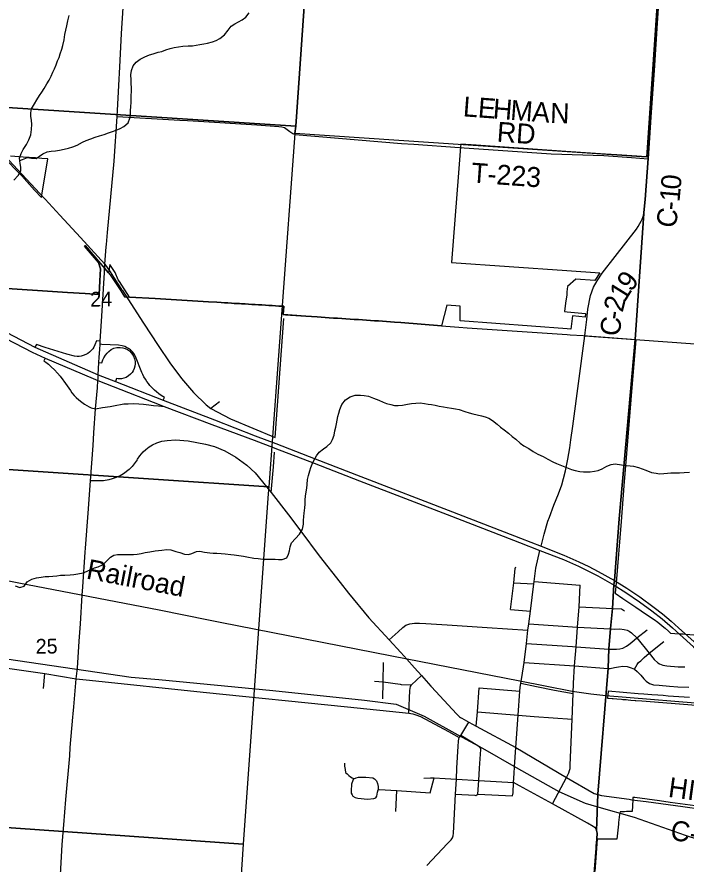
# Model space of a CAD drawing. Extents: x 114843 to 284848, y 317643 to 566895.
# Drawn here: x 253253 to 263305, y 341883 to 354619 of the extents above; entities that cross this region are included whole.
import ezdxf

# ---------------------------------------------------------------- set-up
doc = ezdxf.new("R2010")
doc.units = 0
for name, color, linetype in [('GM_X_City_Street', 7, 'Continuous'), ('GM_X_Corporation', 7, 'Continuous'), ('GM_X_County', 7, 'Continuous'), ('GM_X_County_Road', 7, 'Continuous'), ('GM_X_County_Road_Text', 7, 'Continuous'), ('GM_X_Interchange_Ramps', 7, 'Continuous'), ('GM_X_Minor_River', 7, 'Continuous'), ('GM_X_Rail_Line', 7, 'Continuous'), ('GM_X_Rail_Line_Text', 7, 'Continuous'), ('GM_X_Section', 7, 'Continuous'), ('GM_X_Section_Text', 7, 'Continuous'), ('GM_X_State_Route', 7, 'Continuous'), ('GM_X_Township', 7, 'Continuous'), ('GM_X_Township_Road', 7, 'Continuous'), ('GM_X_Township_Road_Text', 7, 'Continuous'), ('GM_X_US_Route', 7, 'Continuous')]:
    doc.layers.add(name, color=color, linetype=linetype)

msp = doc.modelspace()

# ---------------------------------------------------------------- linework, layer by layer
at = {"layer": 'GM_X_City_Street'}
for p, q in [((257133, 348296), (257263, 350085)), ((261785, 349824), (262542, 349768)), ((256296, 348834), (256164, 348733)), ((260716, 346113), (261017, 346097)), ((261022, 346129), (261713, 346076)), ((260670, 345711), (260966, 345685)), ((261699, 345750), (262204, 345725)), ((261653, 345149), (262147, 345116)), ((253652, 344524), (253674, 344750)), ((260197, 344531), (260809, 344482)), ((259366, 343176), (259468, 343178)), ((259462, 342954), (259519, 343179)), ((258944, 342674), (258960, 342987)), ((259842, 342933), (260131, 342917))]:
    msp.add_line(p, q, dxfattribs=at)
for points in [[(255061, 347963), (255066, 347971), (255101, 348021), (255150, 348079), (255190, 348117), (255241, 348157), (255291, 348185), (255354, 348215), (255430, 348240), (255510, 348253), (255633, 348263), (255826, 348245), (256087, 348197), (256223, 348161), (256377, 348097), (256542, 348000), (256706, 347881), (256834, 347765), (257072, 347471), (257331, 347132), (257517, 346888), (257792, 346519), (258110, 346115), (258232, 345954), (258539, 345587), (258845, 345252), (259019, 345062), (259110, 344962), (259223, 344835), (259330, 344716), (259472, 344559)], [(257072, 347471), (257105, 347855), (257122, 348074)], [(255061, 347963), (255059, 347961), (255028, 347919)], [(255028, 347919), (254984, 347860), (254939, 347813), (254854, 347749), (254801, 347720), (254745, 347694), (254685, 347673), (254631, 347659), (254552, 347645), (254359, 347647)], [(260836, 344690), (260871, 344912), (260906, 345199), (260929, 345401), (260941, 345495), (260966, 345685), (261017, 346097), (261022, 346129), (261046, 346330), (261110, 346598)], [(260670, 345711), (260716, 346113), (260738, 346326), (260749, 346353)], [(261616, 344603), (261630, 344862), (261653, 345149), (261672, 345446), (261699, 345750), (261713, 346076)], [(262204, 345725), (262335, 345719), (262379, 345691)], [(258845, 345252), (258978, 345377), (259049, 345441), (259095, 345474), (259154, 345496), (259225, 345506), (259300, 345503), (259398, 345501), (259717, 345481), (260319, 345441), (260929, 345401)], [(260941, 345495), (261672, 345446), (262172, 345420)], [(262147, 345116), (262261, 345114), (262312, 345117), (262356, 345129), (262411, 345159), (262446, 345185), (262493, 345220), (262566, 345284), (262719, 345406)], [(262172, 345420), (262237, 345417), (262311, 345418), (262375, 345412), (262419, 345401), (262451, 345384), (262488, 345360), (262566, 345284), (262751, 345055), (262828, 344961), (262880, 344911), (262907, 344893), (262958, 344874), (263018, 344865), (263188, 344851), (263288, 344847)], [(260906, 345199), (261600, 345153), (261653, 345149)], [(262529, 344811), (262571, 344884), (262593, 344912), (262624, 344941), (262677, 344988), (262751, 345055), (262971, 345227)], [(258750, 344365), (258754, 344624), (258759, 344914)], [(260871, 344912), (261630, 344862), (262134, 344826)], [(262134, 344826), (262167, 344824), (262228, 344837), (262290, 344851), (262356, 344857), (262422, 344852), (262481, 344835), (262529, 344811), (262572, 344779), (262626, 344725), (262672, 344668), (262707, 344632), (262755, 344599), (262817, 344577), (262903, 344571), (263056, 344557), (263184, 344549), (263348, 344542)], [(258625, 344633), (258754, 344624), (259010, 344588)], [(259140, 344151), (259155, 344492), (259163, 344552), (259178, 344577), (259330, 344716)], [(260747, 343636), (260783, 344122), (260809, 344482), (260813, 344537), (260822, 344601), (260836, 344690)], [(259010, 344588), (259027, 344585), (259178, 344577)], [(259472, 344559), (259483, 344547), (259855, 344140), (259880, 344118), (259902, 344098), (259917, 344088), (259937, 344076), (260040, 344017)], [(260152, 343955), (260173, 344174), (260197, 344531)], [(260822, 344601), (261058, 344553), (261328, 344497), (261608, 344447)], [(261298, 342787), (261428, 343034), (261509, 343183), (261542, 343256), (261553, 343288), (261562, 343318), (261565, 343370), (261592, 344063), (261608, 344447), (261616, 344603)], [(260173, 344174), (260783, 344122), (261024, 344102), (261592, 344063)], [(259885, 343727), (259885, 343738), (259896, 343784), (259921, 343816), (260040, 344017)], [(260040, 344017), (260152, 343955), (260747, 343636)], [(260220, 343611), (260217, 343624), (260202, 343641), (260176, 343659), (259921, 343816)], [(259410, 341863), (259722, 342191), (259776, 342248), (259794, 342276), (259806, 342307), (259809, 342349), (259842, 342933), (259855, 343160), (259863, 343325), (259882, 343656), (259885, 343727)], [(260747, 343636), (261509, 343183), (261927, 342946), (261981, 342930)], [(260176, 342932), (260193, 343139), (260204, 343327), (260221, 343606), (260220, 343611)], [(258172, 343398), (258172, 343354), (258182, 343304), (258190, 343262), (258212, 343242), (258238, 343214), (258264, 343196), (258290, 343178), (258310, 343168), (258316, 343164), (258349, 343182), (258385, 343192), (258423, 343192), (258495, 343190), (258597, 343179), (258623, 343165), (258653, 343135), (258671, 343095), (258681, 343047), (258679, 343000)], [(258310, 343168), (258297, 343138), (258281, 343086), (258273, 342986), (258274, 342962), (258275, 342950), (258289, 342924), (258299, 342906), (258335, 342882), (258373, 342872), (258517, 342860), (258615, 342868), (258643, 342880), (258657, 342902), (258669, 342962), (258679, 343000), (258695, 343004), (258960, 342987), (259462, 342954)], [(259468, 343178), (259519, 343179), (259684, 343171), (259855, 343160), (260193, 343139), (260715, 343110)], [(260700, 342910), (260709, 342952), (260715, 343110)], [(260131, 342917), (260145, 342916), (260176, 342932), (260700, 342910)], [(261964, 342260), (261971, 342344), (261963, 342385)]]:
    msp.add_lwpolyline(points, dxfattribs=at)
at = {"layer": 'GM_X_Corporation'}
for points in [[(262912, 355132), (262872, 354526), (262825, 353814), (262768, 352973), (262738, 352513), (262709, 352516), (262565, 352526), (262415, 352536), (262266, 352546), (262095, 352558), (261946, 352568), (261500, 352598), (260150, 352689), (259920, 352706), (259918, 352665), (259887, 352275), (259781, 350929), (261513, 350807), (262010, 350772), (261936, 350656), (261650, 350676), (261524, 350566), (261515, 350487), (261512, 350443), (261495, 350317), (261480, 350192), (261517, 350188), (261796, 350163), (261790, 350107), (261598, 350125), (261573, 349927), (261519, 349930), (259912, 350048), (259912, 350272), (259709, 350285), (259632, 349973), (259018, 350024), (258925, 350031), (258863, 350035), (258803, 350039), (258743, 350043), (258684, 350048), (258624, 350052), (258564, 350056), (258504, 350060), (258444, 350064), (258384, 350068), (258319, 350072), (258259, 350076), (258195, 350081), (258135, 350085), (258070, 350089), (258010, 350093), (257945, 350098), (257885, 350102), (257825, 350106), (257761, 350110), (257591, 350122), (257252, 350144), (257260, 350269), (257189, 350273), (257086, 350279), (257036, 350282), (256986, 350285), (256930, 350289), (256880, 350292), (256831, 350295), (256781, 350298), (256731, 350301), (256681, 350304), (256625, 350307), (256598, 350309), (256575, 350310), (256525, 350313), (256516, 350313), (256475, 350316), (256419, 350319), (256369, 350322), (256319, 350325), (256257, 350329), (256128, 350337), (255328, 350384), (254943, 350408), (254791, 350641), (254774, 350668), (254730, 350778), (254650, 350896), (254630, 350771), (254497, 350926), (254277, 351184), (254265, 351174), (254479, 350926), (254506, 350834), (254497, 350654), (254487, 350446), (254278, 350459), (254014, 350477), (253636, 350502), (252565, 350573)], [(253031, 352533), (253325, 352228), (253518, 352014), (253620, 351903), (253631, 351976), (253635, 351998), (253716, 352486), (253624, 352492), (253530, 352499), (253344, 352511), (253158, 352524)], [(252565, 350573), (253636, 350502), (254014, 350477), (254278, 350459), (254487, 350446), (254497, 350654), (254506, 350834), (254479, 350926), (254265, 351174), (254277, 351184), (254653, 350744), (254712, 350654), (254802, 350515), (254828, 350476), (254870, 350411), (254905, 350410), (254943, 350408), (255328, 350384), (256128, 350337), (256257, 350329), (256319, 350325), (256369, 350322), (256419, 350319), (256475, 350316), (256516, 350313), (256525, 350313), (256575, 350310), (256598, 350309), (256625, 350307), (256681, 350304), (256731, 350301), (256781, 350298), (256831, 350295), (256880, 350292), (256930, 350289), (256986, 350285), (257036, 350282), (257086, 350279), (257189, 350273), (257260, 350269), (257252, 350144), (257285, 350142), (257591, 350122), (257761, 350110), (257825, 350106), (257885, 350102), (257945, 350098), (258010, 350093), (258070, 350089), (258135, 350085), (258195, 350081), (258259, 350076), (258319, 350072), (258384, 350068), (258444, 350064), (258504, 350060), (258564, 350056), (258624, 350052), (258684, 350048), (258743, 350043), (258803, 350039), (258863, 350035), (258925, 350031), (259018, 350024), (259632, 349973), (259892, 349954), (260019, 349945), (261520, 349845), (261562, 349842), (261758, 349829), (262551, 349769), (262477, 348862), (262411, 348054), (262372, 347569), (262329, 347033), (262254, 346109), (262241, 345954), (262356, 345877), (262552, 345746), (262713, 345634), (262825, 345558), (262882, 345519), (262972, 345443), (262989, 345428), (263042, 345384), (263073, 345357), (263201, 345347), (263264, 345343), (263303, 345340), (263544, 345321)], [(263357, 344386), (263278, 344392), (263198, 344398), (263118, 344404), (263038, 344410), (262959, 344417), (262879, 344423), (262789, 344430), (262672, 344439), (262585, 344445), (262133, 344481), (262128, 344426), (262125, 344376), (262195, 344371), (262210, 344370), (262265, 344365), (262335, 344360), (262355, 344358), (262404, 344355), (262434, 344352), (262474, 344349), (262539, 344344), (262544, 344344), (262553, 344343), (262639, 344336), (262706, 344331), (263016, 344307), (263707, 344254)], [(263819, 342708), (263065, 342810), (262908, 342832), (262538, 342882), (262507, 342885), (262506, 342856), (262499, 342757), (262494, 342674), (262482, 342674), (262436, 342673), (262409, 342672), (262379, 342671), (262333, 342670), (262314, 342670), (262305, 342627), (262292, 342506), (262289, 342482), (262266, 342260), (261984, 342260), (261970, 342260), (261934, 341774)]]:
    msp.add_lwpolyline(points, dxfattribs=at)
at = {"layer": 'GM_X_County'}
for points in [[(262910, 355135), (262821, 353807), (262736, 352491), (262692, 351874), (262671, 351678), (262670, 351665), (262541, 349771), (262299, 347075), (262228, 346149), (262222, 346080), (262202, 345728), (262171, 345423), (262146, 345119), (262133, 344829), (261980, 342933), (261962, 342388), (261970, 342347), (261963, 342262), (261953, 342120), (261868, 341046)], [(261868, 341046), (261953, 342120), (261963, 342262), (261970, 342347), (261962, 342388), (261980, 342933), (262133, 344829), (262146, 345119), (262171, 345423), (262202, 345728), (262222, 346080), (262228, 346149), (262299, 347075), (262541, 349771), (262670, 351665), (262671, 351678), (262692, 351874), (262736, 352491), (262821, 353807), (262910, 355135)]]:
    msp.add_lwpolyline(points, dxfattribs=at)
at = {"layer": 'GM_X_County_Road'}
for p, q in [((254777, 353492), (254802, 353965)), ((261785, 349824), (261790, 349871)), ((254490, 349502), (254498, 349620)), ((254434, 348728), (254461, 349045)), ((261957, 342154), (261964, 342260))]:
    msp.add_line(p, q, dxfattribs=at)
for points in [[(262737, 352488), (262738, 352505), (262823, 353804), (262911, 355132)], [(254802, 353965), (254823, 354370), (254850, 354755)], [(252064, 353574), (252322, 353311), (252703, 352915), (253131, 352468), (253597, 351965), (253673, 351883), (253676, 351879)], [(254613, 351376), (254711, 352449), (254758, 353124), (254777, 353492)], [(262673, 351667), (262693, 351871), (262727, 352341), (262737, 352488)], [(253676, 351879), (253896, 351639), (254205, 351301), (254573, 350900)], [(261790, 349871), (261812, 350070), (261831, 350225), (261870, 350433), (261917, 350557), (261970, 350653), (262043, 350767), (262240, 351020), (262559, 351429), (262588, 351471), (262613, 351514), (262631, 351549), (262644, 351579), (262654, 351606), (262664, 351636), (262673, 351667)], [(254594, 351165), (254596, 351197), (254613, 351376)], [(254568, 350794), (254573, 350900), (254594, 351165)], [(254573, 350900), (254652, 350787), (254705, 350707), (254824, 350522), (254836, 350504)], [(254498, 349620), (254503, 349699), (254505, 349744), (254526, 350120), (254567, 350779), (254568, 350794)], [(254836, 350504), (254871, 350450), (255154, 350017)], [(255154, 350017), (255374, 349682), (255549, 349417), (255723, 349182), (255907, 348971), (256097, 348787), (256164, 348733)], [(261127, 346664), (261174, 346845), (261229, 347037), (261253, 347100), (261321, 347281), (261390, 347452), (261439, 347584), (261466, 347682), (261493, 347793), (261530, 347973), (261560, 348142), (261576, 348261), (261604, 348466), (261785, 349824)], [(254471, 349171), (254475, 349238), (254485, 349423), (254490, 349502)], [(254461, 349045), (254470, 349153), (254471, 349171)], [(256164, 348733), (256462, 348575), (257133, 348296)], [(251405, 345206), (251557, 345182), (251716, 345142), (251948, 345068), (252208, 344988), (252355, 344948), (252541, 344908), (253674, 344750), (254143, 344668)], [(254143, 344668), (254344, 344648), (256051, 344467), (258218, 344247), (259140, 344151), (259198, 344140), (259243, 344129), (259314, 344102), (259735, 343874), (259896, 343784)], [(260724, 343243), (260730, 343343), (260747, 343636)], [(260804, 343060), (260715, 343110), (260724, 343243)], [(261964, 342260), (261971, 342344), (261963, 342385), (261943, 342421), (261927, 342437), (261909, 342448), (261825, 342500), (261298, 342787), (260804, 343060)], [(261981, 342930), (262034, 342914), (262449, 342857)], [(262449, 342857), (262491, 342851), (262707, 342823), (263259, 342747), (263826, 342668), (264118, 342627), (264345, 342595), (264523, 342570), (264669, 342554), (264849, 342539), (265224, 342513), (265580, 342486)], [(261852, 340796), (261867, 341006), (261869, 341043), (261954, 342118), (261957, 342154)]]:
    msp.add_lwpolyline(points, dxfattribs=at)
at = {"layer": 'GM_X_Interchange_Ramps'}
for points in [[(254505, 349744), (254446, 349748), (254425, 349688), (254410, 349656), (254391, 349628), (254369, 349602), (254342, 349577), (254317, 349559), (254286, 349542), (254248, 349527), (254217, 349520), (254187, 349516), (254156, 349515), (254119, 349519), (254001, 349549), (253675, 349648), (253544, 349694), (253521, 349653)], [(254485, 349423), (254527, 349420), (254545, 349465), (254560, 349494), (254582, 349532), (254607, 349566), (254631, 349591), (254668, 349618), (254709, 349638), (254754, 349650), (254801, 349652), (254844, 349647), (254880, 349635), (254915, 349617), (254942, 349598), (254969, 349571), (254991, 349543), (255005, 349517), (255020, 349479), (255027, 349440), (255028, 349403), (255024, 349367), (255014, 349333), (255000, 349301), (254982, 349273), (254959, 349247), (254929, 349222), (254895, 349201), (254860, 349187), (254825, 349179), (254773, 349178), (254746, 349183), (254731, 349136)], [(255449, 348859), (255467, 348900), (255421, 348929), (255383, 348955), (255349, 348981), (255318, 349007), (255283, 349041), (255249, 349079), (255227, 349107), (255203, 349139), (255183, 349171), (255161, 349211), (255144, 349244), (255131, 349275), (255032, 349515), (255013, 349553), (254986, 349588), (254961, 349613), (254928, 349637), (254900, 349652), (254871, 349664), (254833, 349673), (254779, 349684), (254529, 349697), (254503, 349699)], [(253675, 349487), (253659, 349451), (253687, 349431), (253728, 349397), (253769, 349361), (253815, 349316), (253862, 349265), (253902, 349217), (253941, 349165), (253957, 349141)], [(253957, 349141), (254055, 349002), (254079, 348968), (254111, 348929), (254143, 348896), (254181, 348863), (254228, 348829), (254267, 348799), (254304, 348776), (254337, 348758), (254367, 348742), (254434, 348728)]]:
    msp.add_lwpolyline(points, dxfattribs=at)
at = {"layer": 'GM_X_Minor_River'}
for points in [[(253206, 352167), (253270, 352235), (253310, 352305), (253313, 352361), (253299, 352415), (253291, 352497), (253314, 352566), (253348, 352626), (253396, 352702), (253431, 352770), (253459, 352849), (253471, 352929), (253474, 353007), (253470, 353063), (253462, 353125), (253459, 353177), (253471, 353239), (253515, 353315), (253550, 353372), (253592, 353436), (253628, 353490), (253660, 353542), (253703, 353615), (253739, 353667), (253765, 353727), (253792, 353789), (253818, 353841), (253842, 353898), (253863, 353958), (253885, 354012), (253903, 354064), (253925, 354134), (253942, 354192), (253960, 354273), (253974, 354353), (253987, 354419), (254001, 354485), (254016, 354563), (254036, 354643)], [(253294, 352462), (253335, 352478), (253409, 352508), (253471, 352498), (253541, 352491), (253592, 352527), (253642, 352561), (253706, 352592), (253768, 352602), (253834, 352608), (253894, 352617), (253964, 352631), (254027, 352647), (254091, 352668), (254157, 352694), (254237, 352737), (254295, 352761), (254362, 352787), (254426, 352810), (254494, 352830), (254562, 352852), (254626, 352875), (254686, 352895), (254745, 352919), (254803, 352944), (254857, 352970), (254925, 353027), (254947, 353095), (254958, 353157), (254960, 353209), (254964, 353273), (254967, 353331), (254971, 353385), (254969, 353441), (254973, 353491), (254972, 353551), (254968, 353619), (254968, 353673), (254965, 353749), (254973, 353816), (254999, 353882), (255046, 353938), (255106, 353982), (255174, 354019), (255244, 354049), (255300, 354065), (255373, 354088), (255429, 354102), (255491, 354125), (255557, 354147), (255613, 354161), (255679, 354172), (255747, 354180), (255825, 354184), (255891, 354187), (256002, 354203), (256060, 354214), (256114, 354226), (256192, 354246), (256244, 354265), (256302, 354293), (256371, 354351), (256425, 354422), (256473, 354482), (256526, 354516), (256580, 354545), (256638, 354577), (256690, 354615), (256743, 354680)], [(255378, 346599), (255430, 346605), (255502, 346612), (255564, 346606), (255638, 346582), (255702, 346565), (255768, 346543), (255830, 346539), (255882, 346554), (255948, 346582), (256002, 346586), (256072, 346573), (256148, 346563), (256200, 346559), (256258, 346556), (256322, 346550), (256380, 346546), (256464, 346537), (256518, 346533), (256586, 346523), (256654, 346514), (256708, 346504), (256810, 346484), (256878, 346475), (256946, 346469), (257004, 346467), (257062, 346468), (257131, 346466), (257183, 346460), (257235, 346463), (257305, 346487), (257333, 346543), (257347, 346595), (257356, 346655), (257376, 346714), (257436, 346776), (257499, 346842), (257541, 346917), (257557, 346993), (257560, 347049), (257562, 347107), (257570, 347159), (257577, 347237), (257581, 347293), (257585, 347361), (257589, 347413), (257600, 347479), (257608, 347536), (257612, 347592), (257617, 347664), (257633, 347726), (257653, 347794), (257669, 347844), (257688, 347894), (257714, 347950), (257754, 348021), (257791, 348075), (257857, 348125), (257907, 348160), (257967, 348214), (257992, 348268), (258016, 348332), (258030, 348395), (258043, 348451), (258051, 348503), (258061, 348555), (258075, 348611), (258088, 348663), (258104, 348719), (258136, 348795), (258189, 348862), (258259, 348906), (258333, 348933), (258413, 348933), (258467, 348929), (258533, 348916), (258611, 348890), (258691, 348858), (258755, 348827), (258807, 348807), (258871, 348791), (258927, 348780), (258979, 348776), (259045, 348782), (259119, 348797), (259181, 348807), (259243, 348815), (259309, 348820), (259377, 348806), (259429, 348798), (259481, 348793), (259537, 348781), (259595, 348769), (259659, 348755), (259717, 348748), (259781, 348738), (259839, 348728), (259895, 348715), (259981, 348689), (260047, 348667), (260103, 348654)], [(260103, 348654), (260165, 348638), (260233, 348620), (260289, 348605), (260343, 348585), (260395, 348551), (260465, 348497), (260519, 348450), (260571, 348410), (260638, 348364), (260694, 348312), (260750, 348273), (260814, 348213), (260870, 348169), (260942, 348130), (261006, 348086), (261079, 348044), (261157, 348009), (261229, 347971), (261305, 347931), (261357, 347904), (261433, 347874), (261507, 347846), (261585, 347813), (261639, 347799), (261709, 347785), (261763, 347782), (261815, 347780), (261867, 347782), (261931, 347790), (261985, 347799), (262045, 347823), (262113, 347865), (262180, 347892), (262240, 347900), (262336, 347886)], [(262336, 347886), (262411, 347876), (262463, 347871), (262517, 347863), (262589, 347843), (262644, 347825), (262702, 347803), (262784, 347772), (262856, 347760), (262907, 347752), (262971, 347754), (263025, 347761), (263077, 347767), (263153, 347763), (263207, 347765), (263279, 347771), (263359, 347774)], [(253225, 346067), (253297, 346043), (253363, 346060), (253408, 346126), (253478, 346168), (253544, 346185), (253618, 346199), (253676, 346208), (253732, 346208), (253792, 346212), (253852, 346219), (253906, 346225), (253971, 346229), (254053, 346234), (254109, 346238), (254169, 346248), (254249, 346261), (254307, 346285), (254365, 346313), (254417, 346336), (254472, 346354), (254540, 346382), (254590, 346429), (254660, 346497), (254709, 346525), (254763, 346538), (254815, 346536), (254869, 346536), (254929, 346535), (255003, 346539), (255057, 346543), (255117, 346554), (255179, 346566), (255251, 346578), (255327, 346591), (255378, 346599)]]:
    msp.add_lwpolyline(points, dxfattribs=at)
at = {"layer": 'GM_X_Rail_Line'}
for points in [[(241236, 347931), (243391, 347940), (243640, 347936), (243821, 347927), (244053, 347906), (244227, 347885), (244482, 347842), (244833, 347775), (245090, 347723), (246389, 347466), (248302, 347094), (248887, 346978), (250263, 346707), (251611, 346444), (253281, 346111), (255388, 345704), (256130, 345556), (256304, 345522), (258885, 345016), (260809, 344636), (261189, 344562), (261594, 344484), (261873, 344442), (262101, 344419)], [(252412, 345068), (254969, 344691), (255383, 344656), (257099, 344495), (258475, 344345), (258952, 344287), (259371, 344106), (259875, 343827), (260245, 343626), (260753, 343334), (261395, 342976), (261789, 342801), (261961, 342747)], [(262101, 344419), (265516, 344139)], [(261961, 342747), (262525, 342586), (263290, 342320), (263906, 342119)]]:
    msp.add_lwpolyline(points, dxfattribs=at)
at = {"layer": 'GM_X_Section'}
for points in [[(252373, 358690), (257805, 358317), (257798, 358098), (257440, 352975), (252018, 353328)], [(257798, 358098), (263067, 357731), (262709, 352509), (257427, 352865), (257440, 352975)], [(252018, 353328), (257440, 352975), (257427, 352865), (257037, 347556), (251608, 347918)], [(251608, 347918), (257037, 347556), (257027, 347454), (256651, 342184), (251239, 342563)], [(251239, 342563), (256651, 342184), (256294, 336768), (250988, 337128), (250870, 337131)]]:
    msp.add_lwpolyline(points, close=True, dxfattribs=at)
at = {"layer": 'GM_X_State_Route'}
for p, q in [((254410, 348367), (254434, 348728)), ((254094, 344091), (254099, 344143))]:
    msp.add_line(p, q, dxfattribs=at)
for points in [[(254434, 348728), (254539, 348745), (254651, 348765), (254751, 348785), (254808, 348794), (254860, 348801), (254925, 348805), (255005, 348807), (255084, 348803), (255153, 348799), (255234, 348788), (255303, 348776), (255378, 348771), (255464, 348764)], [(254359, 347647), (254397, 348175), (254410, 348367)], [(254284, 346634), (254324, 347161), (254359, 347647)], [(254241, 346052), (254279, 346571), (254284, 346634)], [(254143, 344668), (254160, 344829), (254187, 345234), (254207, 345493), (254232, 345925), (254241, 346052)], [(254099, 344143), (254108, 344248), (254143, 344668)], [(253599, 336945), (253596, 337126), (253599, 337215), (253602, 337285), (253607, 337367), (253619, 337506), (253637, 337696), (253673, 338219), (253693, 338542), (253739, 339215), (253768, 339741), (253813, 340494), (253858, 341152), (253897, 341542), (253933, 342176), (253959, 342473), (253989, 342855), (254045, 343512), (254054, 343638), (254094, 344091)]]:
    msp.add_lwpolyline(points, dxfattribs=at)
at = {"layer": 'GM_X_Township'}
for points in [[(261868, 341046), (261953, 342120), (261963, 342262), (261970, 342347), (261962, 342388), (261980, 342933), (262133, 344829), (262146, 345119), (262171, 345423), (262202, 345728), (262222, 346080), (262228, 346149), (262299, 347075), (262541, 349771), (262670, 351665), (262671, 351678), (262692, 351874), (262736, 352491), (262821, 353807), (262910, 355135)], [(262910, 355135), (262821, 353807), (262736, 352491), (262692, 351874), (262671, 351678), (262670, 351665), (262541, 349771), (262299, 347075), (262228, 346149), (262222, 346080), (262202, 345728), (262171, 345423), (262146, 345119), (262133, 344829), (261980, 342933), (261962, 342388), (261970, 342347), (261963, 342262), (261953, 342120), (261868, 341046)]]:
    msp.add_lwpolyline(points, dxfattribs=at)
at = {"layer": 'GM_X_Township_Road'}
for points in [[(254758, 353124), (255699, 353069), (255817, 353062), (255982, 353052), (256857, 352996), (257186, 352974), (257233, 352969), (257270, 352956), (257313, 352929), (257350, 352896), (257397, 352865), (257430, 352850), (259029, 352717), (259217, 352705), (259902, 352658)], [(259902, 352658), (261278, 352563), (262072, 352534), (262485, 352508), (262737, 352488)], [(262542, 349768), (265103, 349585), (265124, 349583)]]:
    msp.add_lwpolyline(points, dxfattribs=at)
at = {"layer": 'GM_X_US_Route'}
for points in [[(245945, 354646), (246232, 354355), (246761, 353811), (247182, 353371), (247405, 353156), (247582, 352997), (247798, 352822), (247999, 352672), (248237, 352514), (248524, 352341), (250105, 351485), (251471, 350750), (252989, 349931), (253521, 349653)], [(251802, 350475), (252947, 349857), (253480, 349579), (253675, 349487), (254398, 349184)], [(253521, 349653), (254475, 349238), (254731, 349136), (255449, 348859), (256221, 348560), (256834, 348321), (257142, 348204), (257734, 347976), (258417, 347711), (259798, 347180), (260819, 346782), (261127, 346664), (261468, 346528), (261692, 346429), (261843, 346357), (261985, 346283), (262229, 346146)], [(254398, 349184), (254470, 349153), (254699, 349062), (255416, 348785), (255464, 348764)], [(255464, 348764), (256183, 348490), (256817, 348255), (257115, 348142)], [(257115, 348142), (257125, 348138), (257717, 347910), (258400, 347645), (259781, 347114), (260802, 346716), (261110, 346598), (261463, 346460), (261687, 346361), (261838, 346289), (261980, 346215), (262223, 346078)], [(262223, 346078), (262402, 345965), (262607, 345827), (262789, 345692), (262944, 345568), (263102, 345433), (263155, 345386)], [(262229, 346146), (262415, 346031), (262609, 345902), (262827, 345743), (262951, 345644), (263079, 345537), (263194, 345436), (263428, 345226)], [(263155, 345386), (263212, 345335), (263415, 345151), (263571, 345013), (263659, 344938), (263743, 344871), (263831, 344805), (263901, 344756), (264008, 344689), (264113, 344627), (264215, 344574), (264322, 344524), (264433, 344477), (264524, 344442), (264617, 344411), (264700, 344383), (264736, 344374)]]:
    msp.add_lwpolyline(points, dxfattribs=at)

# ---------------------------------------------------------------- texts
at = {"layer": 'GM_X_County_Road_Text'}
for s, rotation, p in [('0', 85.1833, (263223, 352016)), ('1', 84.859, (263206, 351830)), ('-', 84.151, (263193, 351703)), ('C', 78.3638, (263139, 351429)), ('9', 52.3717, (262478, 350475)), ('1', 58.1782, (262385, 350324)), ('2', 76.4011, (262352, 350168)), ('-', 81.5504, (262335, 350053)), ('C', 83.9456, (262309, 349811)), ('HILL', 352.2417, (263026, 342895)), ('C-18', 352.1393, (263058, 342248))]:
    msp.add_text(s, height=300, rotation=rotation, dxfattribs=at).set_placement(p)
at = {"layer": 'GM_X_Rail_Line_Text'}
msp.add_text('Railroad', height=299, rotation=349.1338, dxfattribs=at).set_placement((254282, 346178))
at = {"layer": 'GM_X_Section_Text'}
for s, rotation, p in [('24', 0.4145, (254355, 350265)), ('25', 0.4144, (253535, 345047))]:
    msp.add_text(s, height=221, rotation=rotation, dxfattribs=at).set_placement(p)
at = {"layer": 'GM_X_Township_Road_Text'}
for s, rotation, p in [('L', 355.6952, (259947, 353126)), ('E', 355.7005, (260171, 353110)), ('H', 355.6955, (260395, 353093)), ('M', 355.6967, (260658, 353073)), ('A', 355.6955, (260983, 353049)), ('N', 358.0803, (261260, 353028)), ('RD', 355.9788, (260456, 352745)), ('T-223', 355.9303, (260070, 352130))]:
    msp.add_text(s, height=300, rotation=rotation, dxfattribs=at).set_placement(p)

doc.saveas('drawing.dxf')
